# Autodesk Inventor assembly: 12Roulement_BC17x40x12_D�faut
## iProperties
Created: 2011-01
Part Number: 12Roulement_BC17x40x12_D�faut
Document SubType Name: Assembly
Designer: eric
Mass: 8.37238 g
Surface Area: 70.5503 cm^2
Volume: 8.37238 cm^3
Density: 1 g/cm^3
Author: eric
